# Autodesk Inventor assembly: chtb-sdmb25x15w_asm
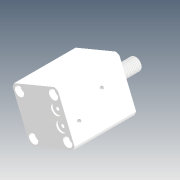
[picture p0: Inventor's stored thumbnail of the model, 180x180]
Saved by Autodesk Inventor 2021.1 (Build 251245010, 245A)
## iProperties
Company: Microsoft
Created: 2018-05
Part Number: chtb-sdmb25x15w_asm
Description: STEP AP214
Document SubType Name: Assembly
Designer: user
Title: chtb-sdmb25x15w_asm.STEP
Author: Windows
Revision Number: ÈÎºÎ
Sending System: SolidWorks 2015
Preprocessor: SwSTEP 2.0
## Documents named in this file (4)
- D:\Vault_2016\Projekty\Clamptek\Hydraulic\CHTB\CHTB-25\Inventor\chtb-sdmb25x15w\chtb-sdmb25x15w_asm.iam
- D:\Vault_2016\Projekty\Clamptek\Hydraulic\CHTB\CHTB-25\Inventor\chtb-sdmb25x15w\CHTB-25QG.ipt
- D:\Vault_2016\Projekty\Clamptek\Hydraulic\CHTB\CHTB-25\Inventor\chtb-sdmb25x15w\CHTB-SDMB25X15NBT.ipt
- D:\Vault_2016\Projekty\Clamptek\Hydraulic\CHTB\CHTB-25\Inventor\chtb-sdmb25x15w\CHTB-SDMB25X15WHSG.ipt
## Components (3 placed, 3 different names)
1. CHTB-25QG_1
2. CHTB-SDMB25X15NBT_2
3. CHTB-SDMB25X15WHSG_3
